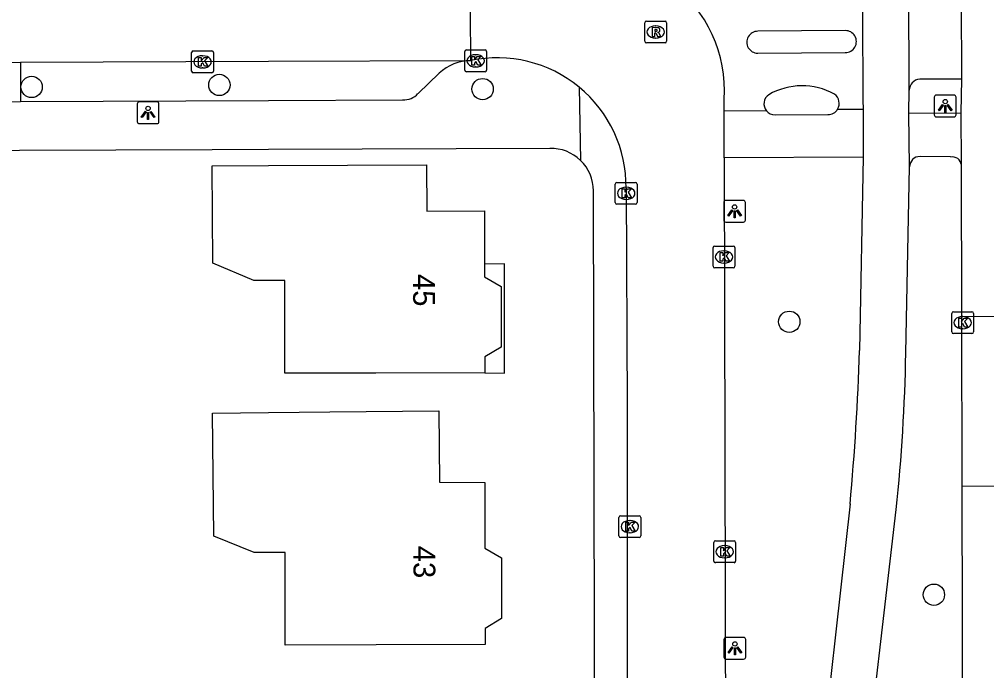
# Model space of a CAD drawing. Extents: x 160457 to 162082, y 388340 to 389736.
# Drawn here: x 160988.58 to 161032.93, y 388665.66 to 388695.52 of the extents above; entities that cross this region are included whole.
import ezdxf

# ---------------------------------------------------------------- set-up
doc = ezdxf.new("R2010")
doc.units = 0
for name, color, linetype in [('IMGEO_Boom', 7, 'Continuous'), ('IMGEO_Fietspad_gesloten', 7, 'Continuous'), ('IMGEO_Fietspad_open', 7, 'Continuous'), ('IMGEO_Kolk', 7, 'Continuous'), ('IMGEO_Lichtpunt', 7, 'Continuous'), ('IMGEO_Muur', 7, 'Continuous'), ('IMGEO_Pand', 7, 'Continuous'), ('IMGEO_Pand_nummerreeks', 7, 'Continuous'), ('IMGEO_Pand_overbouw', 7, 'Continuous'), ('IMGEO_Rijbaan_lokaal_gesloten', 7, 'Continuous'), ('IMGEO_Rijbaan_lokaal_open', 7, 'Continuous'), ('IMGEO_Rioolput', 7, 'Continuous'), ('IMGEO_Voetpad_open', 7, 'Continuous')]:
    doc.layers.add(name, color=color, linetype=linetype)

msp = doc.modelspace()

# ---------------------------------------------------------------- linework, layer by layer
at = {"layer": 'IMGEO_Boom'}
for centre in [(160989.139, 388692.423), (160997.75, 388692.512), (161009.821, 388692.321), (161023.881, 388681.656), (161030.512, 388669.144)]:
    msp.add_circle(centre, 0.489, dxfattribs=at)
at = {"layer": 'IMGEO_Fietspad_gesloten'}
for points in [[(161027.228, 388699.835), (161027.261, 388691.817), (161027.263, 388691.401)], [(161029.379, 388692.268), (161029.363, 388696.883)], [(161029.367, 388691.215), (161029.379, 388692.268)], [(161027.263, 388691.401), (161027.272, 388689.209)], [(161029.394, 388688.752), (161029.367, 388691.215)], [(161027.272, 388689.209), (161027.108, 388680.338)], [(161029.226, 388680.216), (161029.394, 388688.752)], [(161026.668, 388673.304), (161025.126, 388659.527)], [(161027.183, 388659.235), (161028.783, 388673.055)]]:
    msp.add_lwpolyline(points, dxfattribs=at)
for centre, radius, start, end in [((160910.18, 388684.121), 116.989, 354.69454, 358.14671), ((160949.388, 388681.561), 79.849, 353.88506, 359.035)]:
    msp.add_arc(centre, radius, start, end, dxfattribs=at)
at = {"layer": 'IMGEO_Fietspad_open'}
for points in [[(161026.448, 388695.002), (161022.439, 388694.973)], [(161022.437, 388693.971), (161026.452, 388694.001)], [(161031.796, 388692.775), (161029.867, 388692.772)], [(161020.892, 388691.347), (161022.837, 388691.327)], [(161026.098, 388691.402), (161027.263, 388691.401)]]:
    msp.add_lwpolyline(points, dxfattribs=at)
for centre, radius, start, end in [((161022.434, 388694.472), 0.501, 89.43, 270.3413), ((161026.459, 388694.502), 0.501, 269.1514, 91.3065), ((161029.89, 388692.261), 0.511, 92.6009, 179.2472), ((161024.469, 388689.42), 3.054, 60.9914, 119.9616), ((161023.226, 388691.648), 0.505, 124.0299, 219.4928), ((161025.663, 388691.669), 0.51, 328.4714, 55.7749)]:
    msp.add_arc(centre, radius, start, end, dxfattribs=at)
at = {"layer": 'IMGEO_Kolk'}
for p, q in [((160996.479, 388693.144), (160996.479, 388693.996)), ((160996.554, 388694.07), (160997.406, 388694.07)), ((160997.48, 388693.996), (160997.48, 388693.144)), ((161009.003, 388693.193), (161009.003, 388694.045)), ((161009.078, 388694.119), (161009.93, 388694.119)), ((161010.004, 388694.045), (161010.004, 388693.193)), ((160996.967, 388693.85), (160996.992, 388693.85)), ((161009.491, 388693.899), (161009.516, 388693.899)), ((160997.406, 388693.07), (160996.554, 388693.07)), ((160996.99, 388693.29), (160996.965, 388693.29)), ((161009.93, 388693.119), (161009.078, 388693.119)), ((161009.514, 388693.339), (161009.489, 388693.339)), ((161015.905, 388687.118), (161015.905, 388687.97)), ((161015.98, 388688.044), (161016.832, 388688.044)), ((161016.393, 388687.824), (161016.418, 388687.824)), ((161016.906, 388687.97), (161016.906, 388687.118)), ((161016.832, 388687.044), (161015.98, 388687.044)), ((161016.416, 388687.264), (161016.391, 388687.264)), ((161020.464, 388685.128), (161021.316, 388685.128)), ((161020.389, 388684.202), (161020.389, 388685.054)), ((161020.877, 388684.908), (161020.902, 388684.908)), ((161021.39, 388685.054), (161021.39, 388684.202)), ((161020.9, 388684.348), (161020.875, 388684.348)), ((161021.316, 388684.128), (161020.464, 388684.128)), ((161031.33, 388681.19), (161031.33, 388682.042)), ((161031.405, 388682.116), (161032.257, 388682.116)), ((161032.331, 388682.042), (161032.331, 388681.19)), ((161031.818, 388681.896), (161031.843, 388681.896)), ((161032.257, 388681.116), (161031.405, 388681.116)), ((161031.841, 388681.336), (161031.816, 388681.336)), ((161016.072, 388671.839), (161016.072, 388672.691)), ((161016.147, 388672.765), (161016.999, 388672.765)), ((161017.073, 388672.691), (161017.073, 388671.839)), ((161016.56, 388672.545), (161016.585, 388672.545)), ((161016.999, 388671.765), (161016.147, 388671.765)), ((161016.583, 388671.985), (161016.558, 388671.985)), ((161020.421, 388670.689), (161020.421, 388671.541)), ((161020.496, 388671.615), (161021.348, 388671.615)), ((161020.909, 388671.395), (161020.934, 388671.395)), ((161021.422, 388671.541), (161021.422, 388670.689)), ((161021.348, 388670.615), (161020.496, 388670.615)), ((161020.932, 388670.835), (161020.907, 388670.835))]:
    msp.add_line(p, q, dxfattribs=at)
for points in [[(160996.479, 388693.144), (160996.479, 388693.996)], [(160996.554, 388694.07), (160997.406, 388694.07)], [(160997.48, 388693.996), (160997.48, 388693.144)], [(161009.003, 388693.193), (161009.003, 388694.045)], [(161009.078, 388694.119), (161009.93, 388694.119)], [(161010.004, 388694.045), (161010.004, 388693.193)], [(160996.8, 388693.77), (160996.923, 388693.77), (160996.923, 388693.619), (160997.053, 388693.77), (160997.217, 388693.77), (160997.071, 388693.619), (160997.224, 388693.37), (160997.072, 388693.37), (160996.987, 388693.534), (160996.923, 388693.467), (160996.923, 388693.37), (160996.8, 388693.37), (160996.8, 388693.77)], [(161009.324, 388693.819), (161009.447, 388693.819), (161009.447, 388693.668), (161009.577, 388693.819), (161009.741, 388693.819), (161009.595, 388693.668), (161009.748, 388693.419), (161009.596, 388693.419), (161009.511, 388693.583), (161009.447, 388693.516), (161009.447, 388693.419), (161009.324, 388693.419), (161009.324, 388693.819)], [(160997.406, 388693.07), (160996.554, 388693.07)], [(161009.93, 388693.119), (161009.078, 388693.119)], [(161015.905, 388687.118), (161015.905, 388687.97)], [(161015.98, 388688.044), (161016.832, 388688.044)], [(161016.226, 388687.744), (161016.349, 388687.744), (161016.349, 388687.593), (161016.479, 388687.744), (161016.643, 388687.744), (161016.497, 388687.593), (161016.65, 388687.344), (161016.498, 388687.344), (161016.413, 388687.508), (161016.349, 388687.441), (161016.349, 388687.344), (161016.226, 388687.344), (161016.226, 388687.744)], [(161016.906, 388687.97), (161016.906, 388687.118)], [(161016.832, 388687.044), (161015.98, 388687.044)], [(161020.464, 388685.128), (161021.316, 388685.128)], [(161020.389, 388684.202), (161020.389, 388685.054)], [(161020.71, 388684.828), (161020.833, 388684.828), (161020.833, 388684.677), (161020.963, 388684.828), (161021.127, 388684.828), (161020.981, 388684.677), (161021.134, 388684.428), (161020.982, 388684.428), (161020.897, 388684.592), (161020.833, 388684.525), (161020.833, 388684.428), (161020.71, 388684.428), (161020.71, 388684.828)], [(161021.39, 388685.054), (161021.39, 388684.202)], [(161021.316, 388684.128), (161020.464, 388684.128)], [(161031.33, 388681.19), (161031.33, 388682.042)], [(161031.405, 388682.116), (161032.257, 388682.116)], [(161032.331, 388682.042), (161032.331, 388681.19)], [(161031.651, 388681.816), (161031.774, 388681.816), (161031.774, 388681.665), (161031.904, 388681.816), (161032.068, 388681.816), (161031.922, 388681.665), (161032.075, 388681.416), (161031.923, 388681.416), (161031.838, 388681.58), (161031.774, 388681.513), (161031.774, 388681.416), (161031.651, 388681.416), (161031.651, 388681.816)], [(161032.257, 388681.116), (161031.405, 388681.116)], [(161016.072, 388671.839), (161016.072, 388672.691)], [(161016.147, 388672.765), (161016.999, 388672.765)], [(161017.073, 388672.691), (161017.073, 388671.839)], [(161016.393, 388672.465), (161016.516, 388672.465), (161016.516, 388672.314), (161016.646, 388672.465), (161016.81, 388672.465), (161016.664, 388672.314), (161016.817, 388672.065), (161016.665, 388672.065), (161016.58, 388672.229), (161016.516, 388672.162), (161016.516, 388672.065), (161016.393, 388672.065), (161016.393, 388672.465)], [(161016.999, 388671.765), (161016.147, 388671.765)], [(161020.421, 388670.689), (161020.421, 388671.541)], [(161020.496, 388671.615), (161021.348, 388671.615)], [(161021.422, 388671.541), (161021.422, 388670.689)], [(161020.742, 388671.315), (161020.865, 388671.315), (161020.865, 388671.164), (161020.995, 388671.315), (161021.159, 388671.315), (161021.013, 388671.164), (161021.166, 388670.915), (161021.014, 388670.915), (161020.929, 388671.079), (161020.865, 388671.012), (161020.865, 388670.915), (161020.742, 388670.915), (161020.742, 388671.315)], [(161021.348, 388670.615), (161020.496, 388670.615)]]:
    msp.add_lwpolyline(points, dxfattribs=at)
for centre, start, end in [((160996.556, 388693.994), 91.552, 178.448), ((160996.556, 388693.994), 91.552, 178.448), ((160997.404, 388693.994), 1.552, 88.448), ((160997.404, 388693.994), 1.552, 88.448), ((161009.08, 388694.043), 91.552, 178.448), ((161009.08, 388694.043), 91.552, 178.448), ((161009.928, 388694.043), 1.552, 88.448), ((161009.928, 388694.043), 1.552, 88.448), ((160996.556, 388693.146), 181.552, 268.448), ((160996.556, 388693.146), 181.552, 268.448), ((160997.404, 388693.146), 271.552, 358.448), ((160997.404, 388693.146), 271.552, 358.448), ((161009.08, 388693.195), 181.552, 268.448), ((161009.08, 388693.195), 181.552, 268.448), ((161009.928, 388693.195), 271.552, 358.448), ((161009.928, 388693.195), 271.552, 358.448), ((161015.982, 388687.968), 91.552, 178.448), ((161015.982, 388687.968), 91.552, 178.448), ((161016.83, 388687.968), 1.552, 88.448), ((161016.83, 388687.968), 1.552, 88.448), ((161015.982, 388687.12), 181.552, 268.448), ((161015.982, 388687.12), 181.552, 268.448), ((161016.83, 388687.12), 271.552, 358.448), ((161016.83, 388687.12), 271.552, 358.448), ((161020.466, 388685.052), 91.552, 178.448), ((161020.466, 388685.052), 91.552, 178.448), ((161021.314, 388685.052), 1.552, 88.448), ((161021.314, 388685.052), 1.552, 88.448), ((161020.466, 388684.204), 181.552, 268.448), ((161020.466, 388684.204), 181.552, 268.448), ((161021.314, 388684.204), 271.552, 358.448), ((161021.314, 388684.204), 271.552, 358.448), ((161031.407, 388682.04), 91.552, 178.448), ((161031.407, 388682.04), 91.552, 178.448), ((161032.255, 388682.04), 1.552, 88.448), ((161032.255, 388682.04), 1.552, 88.448), ((161031.407, 388681.192), 181.552, 268.448), ((161031.407, 388681.192), 181.552, 268.448), ((161032.255, 388681.192), 271.552, 358.448), ((161032.255, 388681.192), 271.552, 358.448), ((161016.149, 388672.689), 91.552, 178.448), ((161016.149, 388672.689), 91.552, 178.448), ((161016.997, 388672.689), 1.552, 88.448), ((161016.997, 388672.689), 1.552, 88.448), ((161016.149, 388671.841), 181.552, 268.448), ((161016.149, 388671.841), 181.552, 268.448), ((161016.997, 388671.841), 271.552, 358.448), ((161016.997, 388671.841), 271.552, 358.448), ((161020.498, 388671.539), 91.552, 178.448), ((161020.498, 388671.539), 91.552, 178.448), ((161021.346, 388671.539), 1.552, 88.448), ((161021.346, 388671.539), 1.552, 88.448), ((161020.498, 388670.691), 181.552, 268.448), ((161020.498, 388670.691), 181.552, 268.448), ((161021.346, 388670.691), 271.552, 358.448), ((161021.346, 388670.691), 271.552, 358.448)]:
    msp.add_arc(centre, 0.0765, start, end, dxfattribs=at)
for centre, major_axis, ratio, start_param, end_param in [((160996.966, 388693.57), (-0.387, 0.002), 0.722429, 4.712389, 7.853982), ((160996.991, 388693.57), (-0.39, 0.002), 0.717154, 1.570796, 4.712389), ((161009.49, 388693.619), (-0.387, 0.002), 0.722429, 4.712389, 7.853982), ((161009.515, 388693.619), (-0.39, 0.002), 0.717154, 1.570796, 4.712389), ((161016.392, 388687.544), (-0.387, 0.002), 0.722429, 4.712389, 7.853982), ((161016.417, 388687.544), (-0.39, 0.002), 0.717154, 1.570796, 4.712389), ((161020.876, 388684.628), (-0.387, 0.002), 0.722429, 4.712389, 7.853982), ((161020.901, 388684.628), (-0.39, 0.002), 0.717154, 1.570796, 4.712389), ((161031.817, 388681.616), (-0.387, 0.002), 0.722429, 4.712389, 7.853982), ((161031.842, 388681.616), (-0.39, 0.002), 0.717154, 1.570796, 4.712389), ((161016.559, 388672.265), (-0.387, 0.002), 0.722429, 4.712389, 7.853982), ((161016.584, 388672.265), (-0.39, 0.002), 0.717154, 1.570796, 4.712389), ((161020.908, 388671.115), (-0.387, 0.002), 0.722429, 4.712389, 7.853982), ((161020.933, 388671.115), (-0.39, 0.002), 0.717154, 1.570796, 4.712389)]:
    msp.add_ellipse(centre, major_axis=major_axis, ratio=ratio, start_param=start_param, end_param=end_param, dxfattribs=at)
at = {"layer": 'IMGEO_Lichtpunt'}
for p, q in [((160994.886, 388691.735), (160994.078, 388691.735)), ((160994.886, 388691.735), (160994.078, 388691.735)), ((161030.533, 388691.952), (161030.533, 388691.145)), ((161030.533, 388691.952), (161030.533, 388691.145)), ((161031.435, 388692.047), (161030.627, 388692.047)), ((161031.435, 388692.047), (161030.627, 388692.047)), ((161031.529, 388691.145), (161031.529, 388691.952)), ((161031.529, 388691.145), (161031.529, 388691.952)), ((160993.984, 388691.64), (160993.984, 388690.833)), ((160993.984, 388691.64), (160993.984, 388690.833)), ((160994.98, 388690.833), (160994.98, 388691.64)), ((160994.98, 388690.833), (160994.98, 388691.64)), ((161030.627, 388691.051), (161031.435, 388691.051)), ((161030.627, 388691.051), (161031.435, 388691.051)), ((160994.078, 388690.739), (160994.886, 388690.739)), ((160994.078, 388690.739), (160994.886, 388690.739)), ((161020.877, 388687.125), (161020.877, 388686.318)), ((161020.877, 388687.125), (161020.877, 388686.318)), ((161021.779, 388687.22), (161020.971, 388687.22)), ((161021.779, 388687.22), (161020.971, 388687.22)), ((161021.873, 388686.318), (161021.873, 388687.125)), ((161021.873, 388686.318), (161021.873, 388687.125)), ((161020.971, 388686.224), (161021.779, 388686.224)), ((161020.971, 388686.224), (161021.779, 388686.224)), ((161020.888, 388667.093), (161020.888, 388666.286)), ((161020.888, 388667.093), (161020.888, 388666.286)), ((161021.79, 388667.188), (161020.982, 388667.188)), ((161021.79, 388667.188), (161020.982, 388667.188)), ((161021.884, 388666.286), (161021.884, 388667.093)), ((161021.884, 388666.286), (161021.884, 388667.093)), ((161020.982, 388666.192), (161021.79, 388666.192)), ((161020.982, 388666.192), (161021.79, 388666.192))]:
    msp.add_line(p, q, dxfattribs=at)
for points in [[(160994.358, 388691.304), (160994.397, 388691.276), (160994.209, 388691.014), (160994.171, 388691.041), (160994.358, 388691.304)], [(160994.57, 388691.276), (160994.608, 388691.303), (160994.795, 388691.041), (160994.756, 388691.013), (160994.57, 388691.276)], [(161030.907, 388691.616), (161030.946, 388691.588), (161030.758, 388691.326), (161030.72, 388691.353), (161030.907, 388691.616)], [(161031.009, 388691.568), (161031.056, 388691.568), (161031.056, 388691.246), (161031.009, 388691.246), (161031.009, 388691.568)], [(161031.119, 388691.588), (161031.157, 388691.615), (161031.344, 388691.353), (161031.305, 388691.325), (161031.119, 388691.588)], [(160994.46, 388691.256), (160994.507, 388691.256), (160994.507, 388690.934), (160994.46, 388690.934), (160994.46, 388691.256)], [(161021.251, 388686.789), (161021.29, 388686.761), (161021.102, 388686.499), (161021.064, 388686.526), (161021.251, 388686.789)], [(161021.353, 388686.741), (161021.4, 388686.741), (161021.4, 388686.419), (161021.353, 388686.419), (161021.353, 388686.741)], [(161021.463, 388686.761), (161021.501, 388686.788), (161021.688, 388686.526), (161021.649, 388686.498), (161021.463, 388686.761)], [(161021.262, 388666.757), (161021.301, 388666.729), (161021.113, 388666.467), (161021.075, 388666.494), (161021.262, 388666.757)], [(161021.364, 388666.709), (161021.411, 388666.709), (161021.411, 388666.387), (161021.364, 388666.387), (161021.364, 388666.709)], [(161021.474, 388666.729), (161021.512, 388666.756), (161021.699, 388666.494), (161021.66, 388666.466), (161021.474, 388666.729)]]:
    msp.add_lwpolyline(points, dxfattribs=at)
for centre in [(161031.032, 388691.75), (160994.483, 388691.438), (161021.376, 388686.923), (161021.387, 388666.891)]:
    msp.add_circle(centre, 0.0994, dxfattribs=at)
for centre, start, end in [((160994.078, 388691.64), 90, 180), ((160994.078, 388691.64), 90, 180), ((160994.886, 388691.64), 0, 90), ((160994.886, 388691.64), 0, 90), ((161030.627, 388691.952), 90, 180), ((161030.627, 388691.952), 90, 180), ((161031.435, 388691.952), 0, 90), ((161031.435, 388691.952), 0, 90), ((161030.627, 388691.145), 180, 270), ((161030.627, 388691.145), 180, 270), ((161031.435, 388691.145), 270, 0), ((161031.435, 388691.145), 270, 360), ((160994.078, 388690.833), 180, 270), ((160994.078, 388690.833), 180, 270), ((160994.886, 388690.833), 270, 0), ((160994.886, 388690.833), 270, 360), ((161020.971, 388687.125), 90, 180), ((161020.971, 388687.125), 90, 180), ((161021.779, 388687.125), 0, 90), ((161021.779, 388687.125), 0, 90), ((161020.971, 388686.318), 180, 270), ((161020.971, 388686.318), 180, 270), ((161021.779, 388686.318), 270, 0), ((161021.779, 388686.318), 270, 360), ((161020.982, 388667.093), 90, 180), ((161020.982, 388667.093), 90, 180), ((161021.79, 388667.093), 0, 90), ((161021.79, 388667.093), 0, 90), ((161020.982, 388666.286), 180, 270), ((161020.982, 388666.286), 180, 270), ((161021.79, 388666.286), 270, 0), ((161021.79, 388666.286), 270, 360)]:
    msp.add_arc(centre, 0.0946, start, end, dxfattribs=at)
at = {"layer": 'IMGEO_Muur'}
msp.add_lwpolyline([(160997.422, 388689.545), (160988.583, 388689.51)], dxfattribs=at)
at = {"layer": 'IMGEO_Pand'}
for points in [[(161000.745, 388683.543), (161000.01, 388683.543), (160999.336, 388683.543), (160997.445, 388684.348), (160997.421, 388688.807), (161000, 388688.819), (161007.252, 388688.852), (161007.262, 388686.723), (161009.911, 388686.736), (161009.913, 388684.299), (161009.913, 388683.717), (161010.664, 388683.268), (161010.666, 388680.488), (161009.916, 388680.047), (161009.916, 388679.309), (161004.917, 388679.306), (161000.747, 388679.303), (161000.745, 388683.543)], [(160997.433, 388677.472), (161000, 388677.498), (161002.813, 388677.527), (161007.812, 388677.579), (161007.846, 388674.301), (161009.921, 388674.283), (161009.928, 388671.284), (161010.68, 388670.836), (161010.687, 388668.056), (161009.937, 388667.593), (161009.939, 388666.857), (161004.94, 388666.845), (161000.77, 388666.835), (161000.76, 388671.085), (161000, 388671.083), (160999.351, 388671.082), (160997.492, 388671.823), (160997.433, 388677.472)]]:
    msp.add_lwpolyline(points, dxfattribs=at)
at = {"layer": 'IMGEO_Pand_overbouw'}
msp.add_lwpolyline([(161009.913, 388684.299), (161009.913, 388683.717), (161010.664, 388683.268), (161010.666, 388680.488), (161009.916, 388680.047), (161009.916, 388679.309), (161010.823, 388679.3), (161010.824, 388684.309)], close=True, dxfattribs=at)
at = {"layer": 'IMGEO_Rijbaan_lokaal_gesloten'}
for points in [[(161031.796, 388692.775), (161031.786, 388696.384)], [(161031.762, 388691.227), (161031.796, 388692.775)], [(161031.774, 388688.847), (161031.762, 388691.227)], [(161031.791, 388681.902), (161031.774, 388688.847)], [(161031.909, 388629.816), (161031.808, 388674.113)]]:
    msp.add_lwpolyline(points, dxfattribs=at)
at = {"layer": 'IMGEO_Rijbaan_lokaal_open'}
for points in [[(161009.273, 388693.63), (161009.246, 388697.99)], [(160979.77, 388693.523), (160988.624, 388693.555)], [(160988.624, 388693.555), (161000, 388693.596), (161009.273, 388693.63)], [(161020.892, 388691.347), (161020.891, 388691.858)], [(161020.897, 388689.169), (161020.892, 388691.347)], [(161020.897, 388689.169), (161021.024, 388635.135), (161021.035, 388634.236)], [(161016.398, 388687.779), (161016.442, 388677.73), (161016.445, 388673.805), (161016.456, 388665.357), (161016.466, 388661.133), (161016.484, 388653.297), (161016.488, 388649.049), (161016.533, 388634.173)], [(161031.791, 388681.902), (161038.287, 388681.966)], [(161031.808, 388674.113), (161031.791, 388681.902)], [(161038.306, 388674.146), (161031.808, 388674.113)]]:
    msp.add_lwpolyline(points, dxfattribs=at)
for centre, radius, start, end in [((161014.92, 388692.306), 5.988, 355.7132, 54.1002), ((161010.494, 388687.851), 5.907, 50.6293, 101.9286), ((161010.497, 388687.855), 5.902, 359.2611, 50.6224)]:
    msp.add_arc(centre, radius, start, end, dxfattribs=at)
at = {"layer": 'IMGEO_Rioolput'}
for p, q in [((161017.257, 388694.513), (161017.257, 388695.365)), ((161017.332, 388695.439), (161018.184, 388695.439)), ((161018.258, 388695.365), (161018.258, 388694.513)), ((161017.745, 388695.219), (161017.77, 388695.219)), ((161018.184, 388694.439), (161017.332, 388694.439)), ((161017.768, 388694.659), (161017.743, 388694.659))]:
    msp.add_line(p, q, dxfattribs=at)
for points in [[(161017.257, 388694.513), (161017.257, 388695.365)], [(161017.332, 388695.439), (161018.184, 388695.439)], [(161018.258, 388695.365), (161018.258, 388694.513)], [(161017.846, 388695.137), (161017.594, 388695.139), (161017.594, 388694.739)], [(161017.594, 388694.739), (161017.718, 388694.739), (161017.718, 388694.901), (161017.729, 388694.901)], [(161017.772, 388695.058), (161017.718, 388695.058), (161017.718, 388694.977)], [(161017.718, 388694.977), (161017.77, 388694.977)], [(161017.776, 388694.872), (161017.847, 388694.739), (161017.987, 388694.739), (161017.922, 388694.865)], [(161018.184, 388694.439), (161017.332, 388694.439)]]:
    msp.add_lwpolyline(points, dxfattribs=at)
for centre, radius, start, end in [((161017.334, 388695.363), 0.0765, 91.552, 178.448), ((161017.334, 388695.363), 0.0765, 91.552, 178.448), ((161018.182, 388695.363), 0.0765, 1.552, 88.448), ((161018.182, 388695.363), 0.0765, 1.552, 88.448), ((161017.728, 388694.848), 0.0533, 26.0293, 88.6989), ((161017.754, 388695.166), 0.19, 274.7715, 282.9687), ((161017.778, 388694.962), 0.0964, 77.0061, 93.1865), ((161017.792, 388695.019), 0.0378, 276.6634, 79.6772), ((161017.845, 388695.027), 0.109, 350.3612, 89.416), ((161017.843, 388695.027), 0.112, 277.5842, 350.9817), ((161017.827, 388694.812), 0.108, 29.5134, 73.7905), ((161017.334, 388694.515), 0.0765, 181.552, 268.448), ((161017.334, 388694.515), 0.0765, 181.552, 268.448), ((161018.182, 388694.515), 0.0765, 271.552, 358.448), ((161018.182, 388694.515), 0.0765, 271.552, 358.448)]:
    msp.add_arc(centre, radius, start, end, dxfattribs=at)
for centre, major_axis, ratio, start_param, end_param in [((161017.744, 388694.939), (-0.387, 0.002), 0.722429, 4.712389, 7.853982), ((161017.769, 388694.939), (-0.39, 0.002), 0.717154, 1.570796, 4.712389)]:
    msp.add_ellipse(centre, major_axis=major_axis, ratio=ratio, start_param=start_param, end_param=end_param, dxfattribs=at)
at = {"layer": 'IMGEO_Voetpad_open'}
for points in [[(160988.624, 388693.555), (160988.63, 388691.757)], [(161006.858, 388692.114), (161007.825, 388693.052)], [(161014.241, 388692.417), (161014.31, 388689.053)], [(160979.777, 388691.741), (160988.63, 388691.757)], [(160988.63, 388691.757), (161000, 388691.801), (161006.155, 388691.825)], [(161023.23, 388691.145), (161025.657, 388691.158)], [(161029.367, 388691.215), (161031.762, 388691.227)], [(161012.899, 388689.605), (161000, 388689.555), (160997.422, 388689.545), (160988.583, 388689.51), (160980.252, 388689.478), (160980.256, 388689.617), (160891.912, 388689.351)], [(161027.272, 388689.209), (161020.897, 388689.169)], [(161031.276, 388689.21), (161029.878, 388689.235)], [(161015.021, 388633.677), (161014.902, 388687.658)]]:
    msp.add_lwpolyline(points, dxfattribs=at)
for centre, radius, start, end in [((161009.297, 388691.468), 2.162, 90.63, 132.891), ((161006.19, 388692.739), 0.914, 267.7851, 316.9096), ((161023.226, 388691.652), 0.507, 219.882, 270.4199), ((161025.662, 388691.669), 0.511, 269.3966, 328.5139), ((161012.947, 388687.647), 1.958, 45.8763, 91.3916), ((161029.889, 388688.74), 0.496, 91.3176, 178.5639), ((161031.354, 388688.793), 0.424, 7.275, 100.5473), ((161012.95, 388687.653), 1.952, 0.1574, 45.8327)]:
    msp.add_arc(centre, radius, start, end, dxfattribs=at)

# ---------------------------------------------------------------- texts
at = {"layer": 'IMGEO_Pand_nummerreeks'}
for s, rotation, p in [('45', 270.0386, (161006.634, 388683.847)), ('43', 270.1389, (161006.648, 388671.388))]:
    msp.add_text(s, height=1, rotation=rotation, dxfattribs=at).set_placement(p)

doc.saveas('drawing.dxf')
